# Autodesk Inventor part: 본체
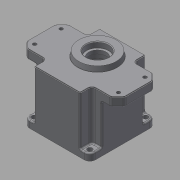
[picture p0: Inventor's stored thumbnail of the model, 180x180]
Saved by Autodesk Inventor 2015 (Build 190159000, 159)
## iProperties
Created: 2016-02
Part Number: 본체
Material: Generic
Document SubType Name: Modeling
Designer: Administrator
Density: 1 g/cm^3
Appearance: Default
Mass: 323.914 g
Surface Area: 757.991 cm^2
Volume: 323.914 cm^3
Author: Administrator
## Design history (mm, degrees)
sketch "Sketch1"
  geometry: L1 (47, -47)-(-47, -47); L2 (-47, -47)-(-47, 47); L3 (-47, 47)-(47, 47); L4 (47, 47)-(47, -47); L5 (47, -47)-(-47, 47); L6 (-47, -47)-(47, 47); 1 further point
  constraints: 12 end point, 2 midpoint, 2 parallel, 1 horizontal, 1 perpendicular
  dimensions: "d0" = 94 distance of L2.end L3.end; "d1" = 94 distance of L3.end L1.start
extrude "Extrusion1" new body sketch "Sketch1" distance "d2" = 67; taper "d3" = 0 deg
fillet "Fillet1" dims "d4" = 8
sketch "Sketch2"
  geometry: L1 (70, -30)-(33, -30); L2 (-70, -30)-(-70, 30); L3 (-70, 30)-(-33, 30); L4 (70, 30)-(70, -30); L5 (70, -30)-(-70, 30); L6 (-70, -30)-(70, 30); L7 (33, -47)-(-33, -47); L8 (-33, -47)-(-33, -30); L9 (-33, 47)-(33, 47); L10 (33, 47)-(33, 30); L11 (33, -47)-(-33, 47); L12 (-33, -47)-(33, 47); L13 (-33, 30)-(33, 30); L14 (-33, 30)-(-33, 47); L15 (-33, -30)-(-33, 30); L16 (33, -30)-(-33, -30); L17 (-33, -30)-(-70, -30); L18 (33, -30)-(33, -47); L19 (33, 30)-(33, -30); L20 (33, 30)-(70, 30); 1 further point
  constraints: 40 end point, 20 parallel, 6 perpendicular, 4 horizontal, 4 midpoint, 1 point on line
  dimensions: "d5" = 140 distance of L2.end L4.start; "d6" = 60 distance of L2.start L2.end; "d7" = 66 distance between parallel lines of L8 L10; "d8" = 94 distance between parallel lines of L7 L9
extrude "Extrusion2" join sketch "Sketch2" distance "d9" = 13; taper "d10" = 0 deg
sketch "Sketch3"
  geometry: L1 (-33, 30)-(-33, 47) reference; L2 (-33, 47)-(-39, 47) reference; L3 (-47, 39)-(-47, 30) reference; L4 (-47, 30)-(-33, 30) reference; L5 (33, 30)-(47, 30) reference; L6 (47, 30)-(47, 39) reference; L7 (39, 47)-(33, 47) reference; L8 (33, 47)-(33, 30) reference; L9 (47, -30)-(33, -30) reference; L10 (33, -30)-(33, -47) reference; L11 (33, -47)-(39, -47) reference; L12 (47, -39)-(47, -30) reference; L13 (-33, -47)-(-33, -30) reference; L14 (-33, -30)-(-47, -30) reference; L15 (-47, -30)-(-47, -39) reference; L16 (-39, -47)-(-33, -47) reference; A1 r 8 centre (-39, 39) between (-39, 47) and (-47, 39) reference; A2 r 8 centre (39, 39) between (47, 39) and (39, 47) reference; A3 r 8 centre (39, -39) between (39, -47) and (47, -39) reference; A4 r 8 centre (-39, -39) between (-47, -39) and (-39, -47) reference; 1 further point
extrude "Extrusion3" cut sketch "Sketch3" distance "d11" = 70; taper "d12" = 0 deg
sketch "Sketch4"
  geometry: C1 r 43 at (0, 0); 1 further point
  constraints: 1 centre point, 1 coincident
  dimensions: "d13" = 86 diameter of C1
extrude "Extrusion4" cut sketch "Sketch4" distance "d14" = 9; taper "d15" = 0 deg
hole "Hole1" diameter "d18" = 80; stored, may be unused: countersink angle "d22" = 90 deg, drill point angle "d24" = 0 deg; dims "d16" = 10, "d17" = 10, "d19" = 6, "d20" = 4, "d21" = 2, "d23" = 62
sketch "Sketch5"
  geometry: C1 r 28 at (0, 11); 1 further point
  constraints: 1 centre point, 1 vertical alignment
  dimensions: "d25" = 11 distance of point (0, 0) C1.centre; "d26" = 56 diameter of C1
extrude "Extrusion5" join sketch "Sketch5" distance "d27" = 7; taper "d28" = -10 deg
hole "Hole3" diameter "d40" = 32; stored, may be unused: countersink angle "d44" = 90 deg, drill point angle "d46" = 0 deg; dims "d38" = 10, "d39" = 10, "d41" = 6, "d42" = 4, "d43" = 2, "d45" = 8
sketch "Sketch8"
  geometry: A1 r 21 centre (0, 11) between (8.978, -7.984) and (-8.978, -7.984); A2 r 15 centre (0, -20) between (0, -5) and (-8.978, -7.984); A3 r 15 centre (0, -20) between (8.978, -7.984) and (0, -5); A4 r 15 centre (0, -20) between (-8.978, -7.984) and (8.978, -7.984); A5 r 21 centre (0, 11) between (-8.978, -7.984) and (8.978, -7.984); 2 further points
  constraints: 10 point on circle, 5 centre point, 2 vertical alignment, 1 coincident, 1 other
  dimensions: "d47" = 42 diameter of A1; "d48" = 20 distance of A2.centre point (0, 0); "d50" = 15 radius of A4
extrude "Extrusion6" join sketch "Sketch8" distance "d51" = 7; taper "d52" = 0 deg
hole "Hole4" diameter "d55" = 25; stored, may be unused: countersink angle "d59" = 90 deg, drill point angle "d61" = 0 deg; dims "d53" = 10, "d54" = 10, "d56" = 6, "d57" = 35, "d58" = 10, "d60" = 15
hole "Hole5" diameter "d64" = 19; stored, may be unused: countersink angle "d68" = 90 deg, drill point angle "d70" = 0 deg; dims "d62" = 10, "d63" = 10, "d65" = 6, "d66" = 22, "d67" = 7, "d69" = 8
fillet "Fillet2" dims "d71" = 1
chamfer "Chamfer1" distance "d72" = 10; stored, may be unused: second distance "d73" = 2, angle "d74" = 45 deg
sketch "Sketch9"
  geometry: A1 r 8 centre (-39, 39) between (-39, 47) and (-47, 39) reference; A2 r 8 centre (39, 39) between (47, 39) and (39, 47) reference; A3 r 8 centre (39, -39) between (39, -47) and (47, -39) reference; A4 r 8 centre (-39, -39) between (-47, -39) and (-39, -47) reference; 5 further points
  constraints: 2 horizontal alignment, 2 vertical alignment
  dimensions: "d125" = 40 horizontal distance of point (0, 0) point (-40, 40); "d126" = 80 distance of point (-40, 40) point (40, 40); "d127" = 40 horizontal distance of point (-40, 40) point (0, 0); "d128" = 80 distance of point (-40, -40) point (-40, 40)
hole "Hole6" sketch "Sketch9" at (-40, 40), (-40, -40), (40, -40), (40, 40) diameter "d75" = 7; stored, may be unused: countersink angle "d79" = 90 deg, drill point angle "d81" = 0 deg; dims "d76" = 6, "d77" = 22, "d78" = 7, "d80" = 8
sketch "Sketch10"
  geometry: 5 further points
  constraints: 2 horizontal alignment, 2 vertical alignment
  dimensions: "d82" = 120 distance of point (-60, -19) point (60, -19); "d83" = 60 horizontal distance of point (60, -19) point (0, 0); "d84" = 38 distance of point (60, 19) point (60, -19); "d85" = 19 vertical distance of point (60, -19) point (0, 0)
hole "Hole7" sketch "Sketch10" at (60, -19), (60, 19), (-60, 19), (-60, -19) diameter "d86" = 5; stored, may be unused: countersink angle "d90" = 90 deg, drill point angle "d92" = 0 deg; dims "d87" = 6, "d88" = 9, "d89" = 4, "d91" = 8
sketch "Sketch11" dims "d99" = 72
  geometry: A1 r 4 centre (36, 0) between (35.852, 3.997) and (35.852, -3.997); A2 r 3.5 centre (35.722, 7.495) between (35.852, 3.997) and (39.148, 8.214); A3 r 3.5 centre (35.722, -7.495) between (39.148, -8.214) and (35.852, -3.997); A4 r 40 centre (0, 0) between (39.148, -8.214) and (39.148, 8.214); 3 further points
  constraints: 8 point on circle, 4 centre point, 2 coincident, 2 horizontal alignment, 2 tangent, 7 other
  dimensions: "d100" = 4 radius of A1; "d101" = 3.5 radius of A2; "d102" = 3.5 radius of A3
extrude "Extrusion7" join sketch "Sketch11" stored distance "d103" = 7; taper "d104" = 0 deg
mirror "Mirror1"
sketch "Sketch12"
  geometry: A1 r 4 centre (36, 0) between (35.852, 3.997) and (35.852, -3.997) reference; A2 r 4 centre (-36, 0) between (-35.852, -3.997) and (-35.852, 3.997) reference; 3 further points
  constraints: 2 coincident
hole "Hole8" sketch "Sketch12" at (36, 0), (-36, 0) diameter "d105" = 3.242; stored, may be unused: countersink angle "d109" = 90 deg, drill point angle "d111" = 118 deg; dims "d106" = 7, "d107" = 9, "d108" = 4, "d110" = 9
sketch "Sketch13" dims "d0" = 94, "d1" = 94
  geometry: L1 (0, 0)-(78, 0) reference; 3 further points
  constraints: 1 midpoint, 1 vertical alignment, 1 other
  dimensions: "d112" = 40 distance of point (39, 0) point (39, -40)
emboss "Emboss1" sketch "Sketch13" dims "d0" = 94, "d1" = 94, "d113" = 0.5, "d114" = 0
fillet "Fillet3" dims "d115" = 0.3
fillet "Fillet6" dims "d121" = 3
fillet "Fillet4" dims "d119" = 5
fillet "Fillet5" dims "d120" = 2
chamfer "Chamfer2" distance "d116" = 1; stored, may be unused: second distance "d117" = 2, angle "d118" = 45 deg
sketch "Sketch14"
  geometry: L1 (33, -45)-(33, -35) reference; L2 (38, -30)-(57.929, -30) reference; L3 (68.536, -21.464)-(61.464, -28.536) reference; L4 (70, -17.929)-(70, 17.929) reference; L5 (61.464, 28.536)-(68.536, 21.464) reference; L6 (57.929, 30)-(38, 30) reference; L7 (33, 35)-(33, 45) reference; L8 (31, 47)-(-31, 47) reference; L9 (-33, 45)-(-33, 35) reference; L10 (-38, 30)-(-57.929, 30) reference; L11 (-68.536, 21.464)-(-61.464, 28.536) reference; L12 (-70, 17.929)-(-70, -17.929) reference; L13 (-61.464, -28.536)-(-68.536, -21.464) reference; L14 (-57.929, -30)-(-38, -30) reference; L15 (-33, -35)-(-33, -45) reference; L16 (-31, -47)-(31, -47) reference; L17 (-31, 46)-(31, 46); L18 (32, 45)-(32, 35); L19 (38, 29)-(57.929, 29); L20 (60.757, 27.828)-(67.828, 20.757); L21 (69, 17.929)-(69, -17.929); L22 (67.828, -20.757)-(60.757, -27.828); L23 (57.929, -29)-(38, -29); L24 (32, -35)-(32, -45); L25 (31, -46)-(-31, -46); L26 (-32, -45)-(-32, -35); L27 (-38, -29)-(-57.929, -29); L28 (-60.757, -27.828)-(-67.828, -20.757); L29 (-69, -17.929)-(-69, 17.929); L30 (-67.828, 20.757)-(-60.757, 27.828); L31 (-57.929, 29)-(-38, 29); L32 (-32, 35)-(-32, 45); C1 r 2.5 at (60, -19) reference; C2 r 2.5 at (-60, 19) reference; C3 r 2.5 at (-60, -19) reference; C4 r 2.5 at (60, 19) reference; A1 r 2 centre (31, -45) between (31, -47) and (33, -45) reference; A2 r 5 centre (38, -35) between (38, -30) and (33, -35) reference; A3 r 5 centre (57.929, -25) between (57.929, -30) and (61.464, -28.536) reference; A4 r 5 centre (65, -17.929) between (68.536, -21.464) and (70, -17.929) reference; A5 r 5 centre (65, 17.929) between (70, 17.929) and (68.536, 21.464) reference; A6 r 5 centre (57.929, 25) between (61.464, 28.536) and (57.929, 30) reference; A7 r 5 centre (38, 35) between (33, 35) and (38, 30) reference; A8 r 2 centre (31, 45) between (33, 45) and (31, 47) reference; A9 r 2 centre (-31, 45) between (-31, 47) and (-33, 45) reference; A10 r 5 centre (-38, 35) between (-38, 30) and (-33, 35) reference; A11 r 5 centre (-57.929, 25) between (-57.929, 30) and (-61.464, 28.536) reference; A12 r 5 centre (-65, 17.929) between (-68.536, 21.464) and (-70, 17.929) reference; A13 r 5 centre (-65, -17.929) between (-70, -17.929) and (-68.536, -21.464) reference; A14 r 5 centre (-57.929, -25) between (-61.464, -28.536) and (-57.929, -30) reference; A15 r 5 centre (-38, -35) between (-33, -35) and (-38, -30) reference; A16 r 2 centre (-31, -45) between (-33, -45) and (-31, -47) reference; A17 r 1 centre (31, 45) between (32, 45) and (31, 46); A18 r 6 centre (38, 35) between (32, 35) and (38, 29); A19 r 4 centre (57.929, 25) between (60.757, 27.828) and (57.929, 29); A20 r 4 centre (65, 17.929) between (69, 17.929) and (67.828, 20.757); A21 r 4 centre (65, -17.929) between (67.828, -20.757) and (69, -17.929); A22 r 4 centre (57.929, -25) between (57.929, -29) and (60.757, -27.828); A23 r 6 centre (38, -35) between (38, -29) and (32, -35); A24 r 1 centre (31, -45) between (31, -46) and (32, -45); A25 r 1 centre (-31, -45) between (-32, -45) and (-31, -46); A26 r 6 centre (-38, -35) between (-32, -35) and (-38, -29); A27 r 4 centre (-57.929, -25) between (-60.757, -27.828) and (-57.929, -29); A28 r 4 centre (-65, -17.929) between (-69, -17.929) and (-67.828, -20.757); A29 r 4 centre (-65, 17.929) between (-67.828, 20.757) and (-69, 17.929); A30 r 4 centre (-57.929, 25) between (-57.929, 29) and (-60.757, 27.828); A31 r 6 centre (-38, 35) between (-38, 29) and (-32, 35); A32 r 1 centre (-31, 45) between (-31, 46) and (-32, 45); 1 further point
  constraints: 32 end point, 32 point on circle, 16 centre point, 31 other
  dimensions: "d122" = 1 distance between parallel lines of L8 L17
extrude "Extrusion8" cut sketch "Sketch14" distance "d123" = 1; taper "d124" = 0 deg
body "Solid1"
node "Projected Loop1"
node "Projected Loop2"
node "Projected Loop3"
node "Projected Loop4"
node "Projected Loop5"
